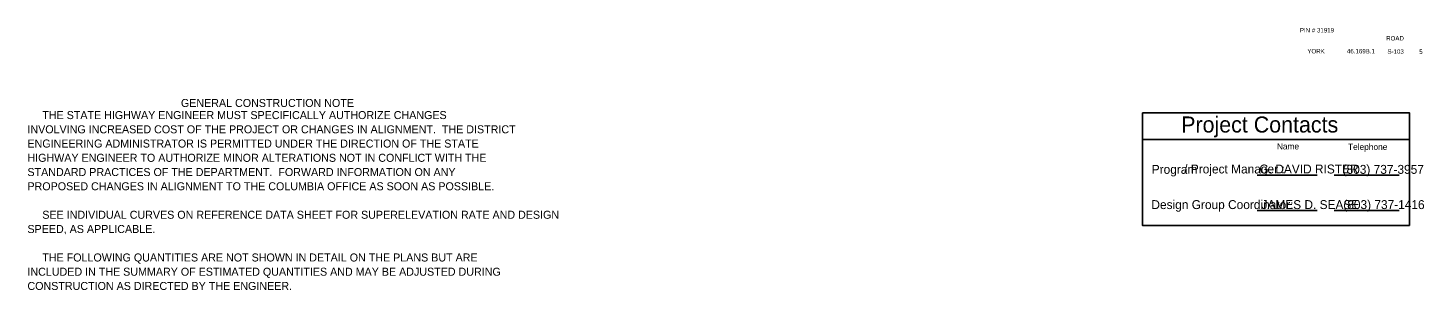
# Model space of a CAD drawing. Extents: x 12719 to 14316, y 14913 to 22622.
# Drawn here: x 12719 to 14289, y 16816 to 17110 of the extents above; entities that cross this region are included whole.
import ezdxf

# ---------------------------------------------------------------- set-up
doc = ezdxf.new("R2010")
doc.units = 0
for name, color, linetype in [('Level 2', 7, 'Continuous'), ('Level 25', 7, 'Continuous'), ('Level 41', 7, 'Continuous')]:
    doc.layers.add(name, color=color, linetype=linetype)

msp = doc.modelspace()

# ---------------------------------------------------------------- linework, layer by layer
at = {"layer": 'Level 2'}
for p, q in [((13972, 16984.7), (14272.2, 16984.7)), ((14100.9, 16944.7), (14168.3, 16944.7)), ((14187.7, 16944.7), (14260.8, 16944.7)), ((14100.9, 16904.7), (14168.3, 16904.7)), ((14187.7, 16904.7), (14260.8, 16904.7))]:
    msp.add_line(p, q, dxfattribs=at)
msp.add_lwpolyline([(13972, 17014.7), (14272.2, 17014.7), (14272.2, 16888.1), (13972, 16888.1)], close=True, dxfattribs=at)

# ---------------------------------------------------------------- texts
for s, height, p in [('Project Contacts', 18, (14015.5, 16992.5)), ('Name', 7, (14123.1, 16973.5)), ('Telephone', 7, (14203.1, 16972.9)), ('Program', 10, (13982.4, 16946.1)), ('/ Project Manager :', 10, (14018.9, 16946.5)), ('Design Group Coordinator:', 10, (13982, 16906.5))]:
    msp.add_text(s, height=height, dxfattribs=at).set_placement(p)
at = {"layer": 'Level 25'}
for s, p in [('GENERAL CONSTRUCTION NOTE', (12890.7, 17021.2)), ('     THE STATE HIGHWAY ENGINEER MUST SPECIFICALLY AUTHORIZE CHANGES', (12718.1, 17007.6)), ('INVOLVING INCREASED COST OF THE PROJECT OR CHANGES IN ALIGNMENT.  THE DISTRICT', (12718.1, 16991.6)), ('ENGINEERING ADMINISTRATOR IS PERMITTED UNDER THE DIRECTION OF THE STATE', (12718.1, 16975.6)), ('HIGHWAY ENGINEER TO AUTHORIZE MINOR ALTERATIONS NOT IN CONFLICT WITH THE ', (12718.1, 16959.6)), ('STANDARD PRACTICES OF THE DEPARTMENT.  FORWARD INFORMATION ON ANY ', (12718.1, 16943.6)), ('PROPOSED CHANGES IN ALIGNMENT TO THE COLUMBIA OFFICE AS SOON AS POSSIBLE.', (12718.1, 16927.6)), ('     SEE INDIVIDUAL CURVES ON REFERENCE DATA SHEET FOR SUPERELEVATION RATE AND DESIGN', (12718.1, 16895.6)), ('SPEED, AS APPLICABLE.', (12718.1, 16879.6)), ('     THE FOLLOWING QUANTITIES ARE NOT SHOWN IN DETAIL ON THE PLANS BUT ARE', (12718.1, 16847.6)), ('INCLUDED IN THE SUMMARY OF ESTIMATED QUANTITIES AND MAY BE ADJUSTED DURING', (12718.1, 16831.6)), ('CONSTRUCTION AS DIRECTED BY THE ENGINEER.', (12718.1, 16815.6))]:
    msp.add_text(s, height=9, dxfattribs=at).set_placement(p)
at = {"layer": 'Level 41'}
for s, height, p in [('PIN # 31919', 5, (14149, 17104.9)), ('ROAD', 5, (14246, 17095.9)), ('YORK', 5, (14157.4, 17081.4)), ('46.169B.1', 5, (14201.9, 17081.4)), ('S-103', 5, (14247.4, 17081)), ('5', 5, (14283.2, 17080.8)), ('G. DAVID RISTER', 10, (14103.5, 16946.5)), ('(803) 737-3957', 10, (14197, 16946.1)), ('JAMES D. SEASE', 10, (14105.8, 16906.5)), ('(803) 737-1416', 10, (14197.8, 16906.5))]:
    msp.add_text(s, height=height, dxfattribs=at).set_placement(p)

doc.saveas('drawing.dxf')
